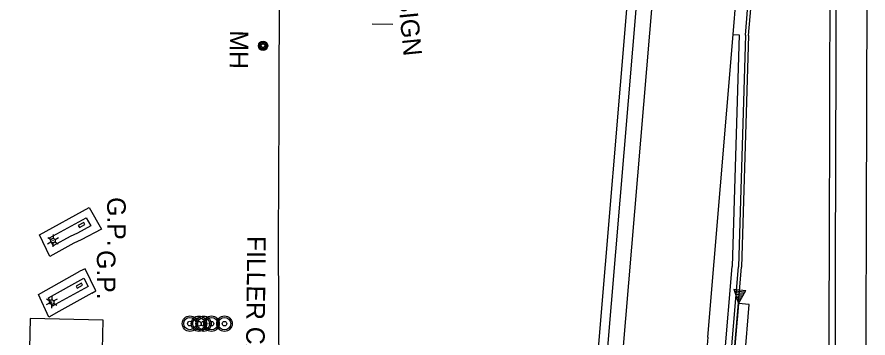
# Model space of a CAD drawing. Extents: x 588843 to 2552415, y 180129 to 269402.
# Drawn here: x 593674 to 593950, y 186246.3 to 186350.4 of the extents above; entities that cross this region are included whole.
import ezdxf

# ---------------------------------------------------------------- set-up
doc = ezdxf.new("R2010")
doc.units = 0
for name, color, linetype in [('Default', 7, 'Continuous'), ('E_BLD_HvyDash', 7, 'Continuous'), ('E_BLD_Vacuum', 7, 'Continuous'), ('E_DWY', 7, 'Continuous'), ('E_LTG', 7, 'Continuous'), ('E_MISCPROP', 7, 'Continuous'), ('E_MISCPROP_Text', 7, 'Continuous'), ('E_SGN', 7, 'Continuous'), ('E_SGN_Text', 7, 'Continuous'), ('E_STRUCT_Joint', 7, 'Continuous'), ('E_UTL_MH', 7, 'Continuous'), ('E_UTL_MH_Text', 7, 'Continuous'), ('P_BMGRD', 7, 'Continuous'), ('P_RDWY_BarrierConc', 7, 'Continuous'), ('P_RDWY_C_and_G', 7, 'Continuous'), ('P_RDWY_C_and_GBack', 7, 'Continuous'), ('P_RDWY_C_and_GFace', 7, 'Continuous'), ('P_RDWY_PavtEdge', 7, 'Continuous'), ('P_RDWY_ShldAgg', 7, 'Continuous'), ('P_RDWY_ShldPaved', 7, 'Continuous')]:
    doc.layers.add(name, color=color, linetype=linetype)

# ---------------------------------------------------------------- blocks, each defined once
blk = doc.blocks.new('SIGN')
at = {"layer": 'Default'}
blk.add_text('SIGN', height=12, dxfattribs=at).set_placement((-18.55, -6))
blk = doc.blocks.new('MHO')
at = {"layer": 'Default'}
for centre, radius in [((0.08, -0.12), 3), ((0.08, -0.12), 2.43), ((0.07, -0.15), 1.94), ((0.02, -0.16), 1.21)]:
    blk.add_circle(centre, radius, dxfattribs=at)
blk = doc.blocks.new('MHT')
at = {"layer": 'E_UTL_MH_Text'}
blk.add_text('MH', height=12, dxfattribs=at).set_placement((-9.81, -6))
blk = doc.blocks.new('FILO')
at = {"layer": 'E_MISCPROP'}
for radius in [5, 4, 1.5]:
    blk.add_circle((0, 0), radius, dxfattribs=at)
blk = doc.blocks.new('FILT_2')
at = {"layer": 'E_MISCPROP_Text'}
blk.add_text('FILLER CAP', height=12, dxfattribs=at).set_placement((10, -6))
blk = doc.blocks.new('LPOL')
at = {"layer": 'Default'}
for p, q in [((-4, 0), (-1.5, 0)), ((-0.75, 1.3), (-2, 3.46)), ((0.75, 1.3), (2, 3.46)), ((1.5, 0), (4, 0)), ((-2, -3.46), (-0.75, -1.3)), ((2, -3.46), (0.75, -1.3))]:
    blk.add_line(p, q, dxfattribs=at)
for radius in [1.5, 1.5, 1.5, 0.125]:
    blk.add_circle((0, 0), radius, dxfattribs=at)
blk = doc.blocks.new('GPO')
at = {"layer": 'E_BLD_Vacuum'}
blk.add_lwpolyline([(0, 0), (4, 0), (4, 1.5), (0, 1.5), (0, 0)], close=True, dxfattribs=at)
blk = doc.blocks.new('GP')
at = {"layer": 'Default'}
blk.add_text('G.P.', height=12, dxfattribs=at).set_placement((-15.36, -6))

msp = doc.modelspace()

# ---------------------------------------------------------------- linework, layer by layer
at = {"layer": 'E_BLD_HvyDash'}
msp.add_lwpolyline([(593697.67, 186061.91), (593701.99, 186252.11), (593678.33, 186252.65), (593674.01, 186062.45), (593697.67, 186061.91)], close=True, dxfattribs=at)
at = {"layer": 'E_DWY'}
for points in [[(593691.75, 186552.08), (593692.17, 186550.27), (593692.81, 186549.4), (593696.11, 186548.65), (593713.81, 186547.81), (593735.44, 186547.41), (593758.31, 186546.06), (593759.53, 186519.34), (593759.38, 186483.93), (593758.86, 186446.35), (593758.89, 186410.14), (593759.07, 186363.78), (593758.91, 186319.14), (593758.71, 186277.58), (593758.99, 186233.19), (593758.98, 186173.88), (593758.89, 186133.64), (593758.82, 186113.71)], [(593698.29, 186260.81), (593687.61, 186254.93), (593684.38, 186253.09), (593681.03, 186260.42), (593694.44, 186267.93)], [(593698.29, 186260.81), (593699.62, 186261.61), (593696.12, 186268.72), (593694.44, 186267.93)]]:
    msp.add_lwpolyline(points, dxfattribs=at)
for points in [[(593692.49, 186277.01), (593684.68, 186272.73), (593681.26, 186279.8), (593697.44, 186288.62), (593701.42, 186281.62), (593694.78, 186278.13), (593692.49, 186277.01)], [(593691.29, 186279.21), (593685.78, 186276.18), (593684.55, 186278.74), (593696.48, 186285.25), (593697.97, 186282.63), (593693.62, 186280.35), (593691.29, 186279.21)], [(593697.09, 186263), (593686.39, 186257.12), (593685.52, 186256.62), (593684.26, 186259.36), (593695.66, 186265.75), (593697.09, 186263)]]:
    msp.add_lwpolyline(points, close=True, dxfattribs=at)
at = {"layer": 'E_SGN'}
msp.add_lwpolyline([(593789.21, 186348.11), (593795.93, 186348.03)], dxfattribs=at)
at = {"layer": 'E_STRUCT_Joint'}
msp.add_lwpolyline([(593897.05, 186232.35), (593898.19, 186246.61)], dxfattribs=at)
at = {"layer": 'P_BMGRD'}
for p, q in [((593906.51, 186262.1), (593908.09, 186257.45)), ((593906.51, 186262.1), (593910.45, 186261.76)), ((593906.69, 186261.58), (593910.18, 186261.28)), ((593906.86, 186261.07), (593909.93, 186260.8)), ((593907.04, 186260.55), (593909.66, 186260.32)), ((593907.21, 186260.03), (593909.4, 186259.84)), ((593907.39, 186259.52), (593909.14, 186259.37)), ((593908.09, 186257.45), (593910.45, 186261.76)), ((593908.09, 186257.45), (593906.21, 186235.71)), ((593907.57, 186259), (593908.88, 186258.88)), ((593908.09, 186257.44), (593907.64, 186252.19)), ((593907.74, 186258.48), (593908.61, 186258.4)), ((593907.92, 186257.96), (593908.35, 186257.93))]:
    msp.add_line(p, q, dxfattribs=at)
at = {"layer": 'P_RDWY_BarrierConc'}
for radius, end in [(137581.12, 180.0810951), (137579.12, 180.081095)]:
    msp.add_arc((731518.05, 185900.98), radius, 179.7862412, end, dxfattribs=at)
at = {"layer": 'P_RDWY_C_and_G'}
for p, q in [((593906.31, 186344.74), (593929.72, 186624.21)), ((593908.3, 186344.58), (593906.03, 186269.5)), ((593906.31, 186344.74), (593908.3, 186344.58)), ((593903.22, 186235.97), (593906.03, 186269.5))]:
    msp.add_line(p, q, dxfattribs=at)
at = {"layer": 'P_RDWY_C_and_GBack'}
for p, q in [((593911.3, 186344.41), (593934.74, 186624.19)), ((593911.3, 186344.41), (593909.03, 186269.33)), ((593906.21, 186235.71), (593909.03, 186269.33))]:
    msp.add_line(p, q, dxfattribs=at)
at = {"layer": 'P_RDWY_C_and_GFace'}
for p, q in [((593910.3, 186344.46), (593933.73, 186624.19)), ((593910.3, 186344.46), (593908.03, 186269.39)), ((593905.21, 186235.78), (593908.03, 186269.39))]:
    msp.add_line(p, q, dxfattribs=at)
at = {"layer": 'P_RDWY_PavtEdge'}
for p, q in [((593870.53, 186241.1), (593888.49, 186455.5)), ((593898.09, 186246.57), (593906.31, 186344.74)), ((593911.52, 186257.15), (593908.03, 186257.45)), ((593909.67, 186235.09), (593911.52, 186257.15))]:
    msp.add_line(p, q, dxfattribs=at)
msp.add_arc((731518.05, 185900.98), 137569.12, 179.769059, 180.0933637, dxfattribs=at)
at = {"layer": 'P_RDWY_ShldAgg'}
msp.add_line((593862.55, 186241.68), (593880.54, 186456.43), dxfattribs=at)
at = {"layer": 'P_RDWY_ShldPaved'}
msp.add_line((593865.49, 186240.75), (593883.52, 186456.08), dxfattribs=at)

# ---------------------------------------------------------------- block references
at = {"layer": 'E_BLD_Vacuum', "xscale": 0.4999999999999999}
for p, yscale, rotation in [((593695.66, 186283.77), 0.49999999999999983, -152.16990441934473), ((593694.94, 186264.08), 0.4999999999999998, -151.83730204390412)]:
    msp.add_blockref('GPO', p, dxfattribs=dict(at, yscale=yscale, rotation=rotation))
at = {"layer": 'E_LTG'}
for p, xscale, yscale, rotation in [((593685.68, 186277.87), 0.5, 0.5, -90.6534731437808), ((593685.26, 186257.97), 0.4999999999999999, 0.4999999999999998, -151.83730204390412)]:
    msp.add_blockref('LPOL', p, dxfattribs=dict(at, xscale=xscale, yscale=yscale, rotation=rotation))
at = {"layer": 'E_MISCPROP', "xscale": 0.5, "yscale": 0.5, "rotation": -90.6534731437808}
for p in [(593730.09, 186250.97), (593733.03, 186250.94), (593734.52, 186250.93), (593737.09, 186250.96), (593741.32, 186250.96)]:
    msp.add_blockref('FILO', p, dxfattribs=at)
at = {"layer": 'E_MISCPROP_Text', "xscale": 0.5, "yscale": 0.5}
for name, p, rotation in [('GP', (593706.28, 186284.29), -89.74305134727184), ('FILT_2', (593751.78, 186284.38), -90.6534731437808), ('GP', (593702.94, 186267.13), -89.74305134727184)]:
    msp.add_blockref(name, p, dxfattribs=dict(at, rotation=rotation))
at = {"layer": 'E_SGN_Text', "xscale": 0.4999999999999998, "yscale": 0.4999999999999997, "rotation": -84.33700075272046}
msp.add_blockref('SIGN', (593801.42, 186348.08), dxfattribs=at)
at = {"layer": 'E_UTL_MH', "xscale": 0.5, "yscale": 0.5, "rotation": -90.6534731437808}
msp.add_blockref('MHO', (593753.88, 186341.09), dxfattribs=at)
at = {"layer": 'E_UTL_MH_Text', "xscale": 0.5, "yscale": 0.5, "rotation": -90.6534731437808}
msp.add_blockref('MHT', (593746.05, 186341.12), dxfattribs=at)

doc.saveas('drawing.dxf')
